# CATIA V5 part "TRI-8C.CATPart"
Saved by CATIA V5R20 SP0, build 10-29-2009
Part number: _TRI-8C
Definition: NONE
Nomenclature: _TRI-8C
Source: Unknown
Description: PART-_TRI-8C-DESC
Bounding box of the stored display mesh (mm): x 0 to 12.3, y -4 to 4, z -4 to 4
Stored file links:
  C:\Users\Utente\Desktop\IO LAVORO\3D X SITO CF\X SITO\PLASTICA\TRI\TRI-8C.CATPart
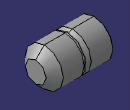
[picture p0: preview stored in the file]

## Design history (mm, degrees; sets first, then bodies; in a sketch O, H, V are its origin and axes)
Body1 "_TRI-8C" (main body)
  Solid1: solid without history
